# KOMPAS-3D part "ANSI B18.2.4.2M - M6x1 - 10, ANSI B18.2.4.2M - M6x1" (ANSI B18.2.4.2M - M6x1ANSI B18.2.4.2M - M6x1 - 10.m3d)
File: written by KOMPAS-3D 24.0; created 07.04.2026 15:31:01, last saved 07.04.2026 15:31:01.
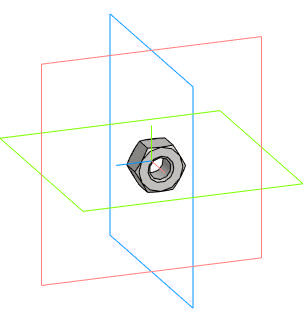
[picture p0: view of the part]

Document properties: Автор: Main; Полное имя файла: D:\DN.ru Аутсерс\Стекло смотровое DN.ru\Исходники\Стекло смотровое DN.ru SG2-34G-F тип В ГОСТ 21836-2021 Ду20 Ру40, углеродистая сталь, фланцевое\ANSI B18.2.4.2M - M6x1ANSI B18.2.4.2M - M6x1 - 10.m3d

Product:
- Body: Solid1  | qty 1
- Part/product: ANSI B18.2.4.2M - M6x1 - 10  | designation ANSI B18.2.4.2M - M6x1
    Комментарий: Типы метрических   шестигранных гаек   2
    additional columns: Сталь, мягкая

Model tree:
1. Solid1  (labels: Solid1)

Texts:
  ANSI B18.2.4.2M - M6x1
